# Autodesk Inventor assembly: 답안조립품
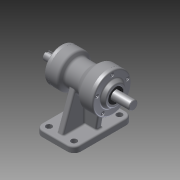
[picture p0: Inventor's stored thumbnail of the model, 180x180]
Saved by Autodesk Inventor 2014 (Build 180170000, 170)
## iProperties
Created: 2015-08
Part Number: 답안조립품
Document SubType Name: Assembly
Designer: user
Author: user
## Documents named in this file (10)
- C:\Users\user\Desktop\450806V1015\450806V1015\답안조립품.iam
- C:\Users\user\Desktop\450806V1015\450806V1015\M4x0.5.ipt
- C:\Users\user\Desktop\450806V1015\450806V1015\뒤커버.ipt
- C:\Users\user\Desktop\450806V1015\450806V1015\베어링 6203.ipt
- C:\Users\user\Desktop\450806V1015\450806V1015\베어링 6205.ipt
- C:\Users\user\Desktop\450806V1015\450806V1015\앞커버.ipt
- C:\Users\user\Desktop\450806V1015\450806V1015\오일실 .ipt
- 오일실 .ipt
- C:\Users\user\Desktop\450806V1015\450806V1015\축.ipt
- C:\Users\user\Desktop\450806V1015\450806V1015\본체.ipt
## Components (10 placed, 1 different names)
1. M4x0.5:1 — Insert:1
2. M4x0.5:2 — Insert:3
3. M4x0.5:3 — Insert:4
4. M4x0.5:4 — Insert:5
5. M4x0.5:5 — Insert:2
6. M4x0.5:6 — Insert:8
7. M4x0.5:7 — Insert:9
8. M4x0.5:8 — Insert:7
9. M4x0.5:9 — Insert:10
10. M4x0.5:10 — Insert:6
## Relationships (10: Insert 10)
- Insert:1: M4x0.5:1
- Insert:2: M4x0.5:5
- Insert:3: M4x0.5:2
- Insert:4: M4x0.5:3
- Insert:5: M4x0.5:4
- Insert:6: M4x0.5:10
- Insert:7: M4x0.5:8
- Insert:8: M4x0.5:6
- Insert:9: M4x0.5:7
- Insert:10: M4x0.5:9
